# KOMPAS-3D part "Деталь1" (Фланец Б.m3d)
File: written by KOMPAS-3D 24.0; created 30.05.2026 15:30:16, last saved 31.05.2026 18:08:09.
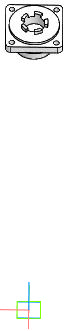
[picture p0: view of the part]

Document properties: Автор: R2D2; Полное имя файла: E:\Работа\Зайцев\GVWR2121M-2W-F-ОСТ Задвижка клиновая 30с964нж DN.ru Ду50-300 Ру25\исходные материалы\DN200\Фланец Б.m3d

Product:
- Body: Твердое тело1  | qty 1
    Масса: 4.33179
- Part/product: Деталь1
    Масса: 4.33179
    additional columns: Типовые

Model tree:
1. Твердое тело1  (labels: Твердое тело1)
2. Эскиз:1  (labels: Грань.Твердое тело1; Вершина.Твердое тело1)
3. Элемент вращения:1
     Угол 1 = 360
4. Эскиз:2  (labels: Грань.Твердое тело1; Ребро.Твердое тело1)
5. Эскиз:3  (labels: Грань.Твердое тело1; Ребро.Твердое тело1)
6. Элемент выдавливания:1
     Расстояние 1 = 10
7. Элемент выдавливания:2  (labels: Грань.Твердое тело1)
     Расстояние 2 = 7
8. Эскиз:4  (labels: Грань.Твердое тело1; Ребро.Твердое тело1)
9. Элемент выдавливания:3  (labels: Грань.Твердое тело1)
     Расстояние 1 = 16
10. Эскиз:5  (labels: Грань.Твердое тело1; Ребро.Твердое тело1)
11. Элемент выдавливания:4
     Расстояние 1 = 7
12. Скругление:1  (with: Ребро.Элемент вращения:1)
     Радиус = 10
13. Скругление:2  (with: Грань.Элемент вращения:1)
     Радиус = 10
14. Элемент выдавливания:5  (labels: Грань.Твердое тело1)
     Расстояние 1 = 1
15. Эскиз:6  (labels: Грань.Твердое тело1; Ребро.Твердое тело1)
16. Элемент выдавливания:7  (with: Грань.Элемент выдавливания:4)
     Расстояние 1 = -8
17. Массив по концентрической сетке:1  (with: Элемент выдавливания:7, Эскиз:6, Грань.Элемент выдавливания:4)  (5 pattern instances)
     Шаг 2 = 360

Expressions: 59/2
